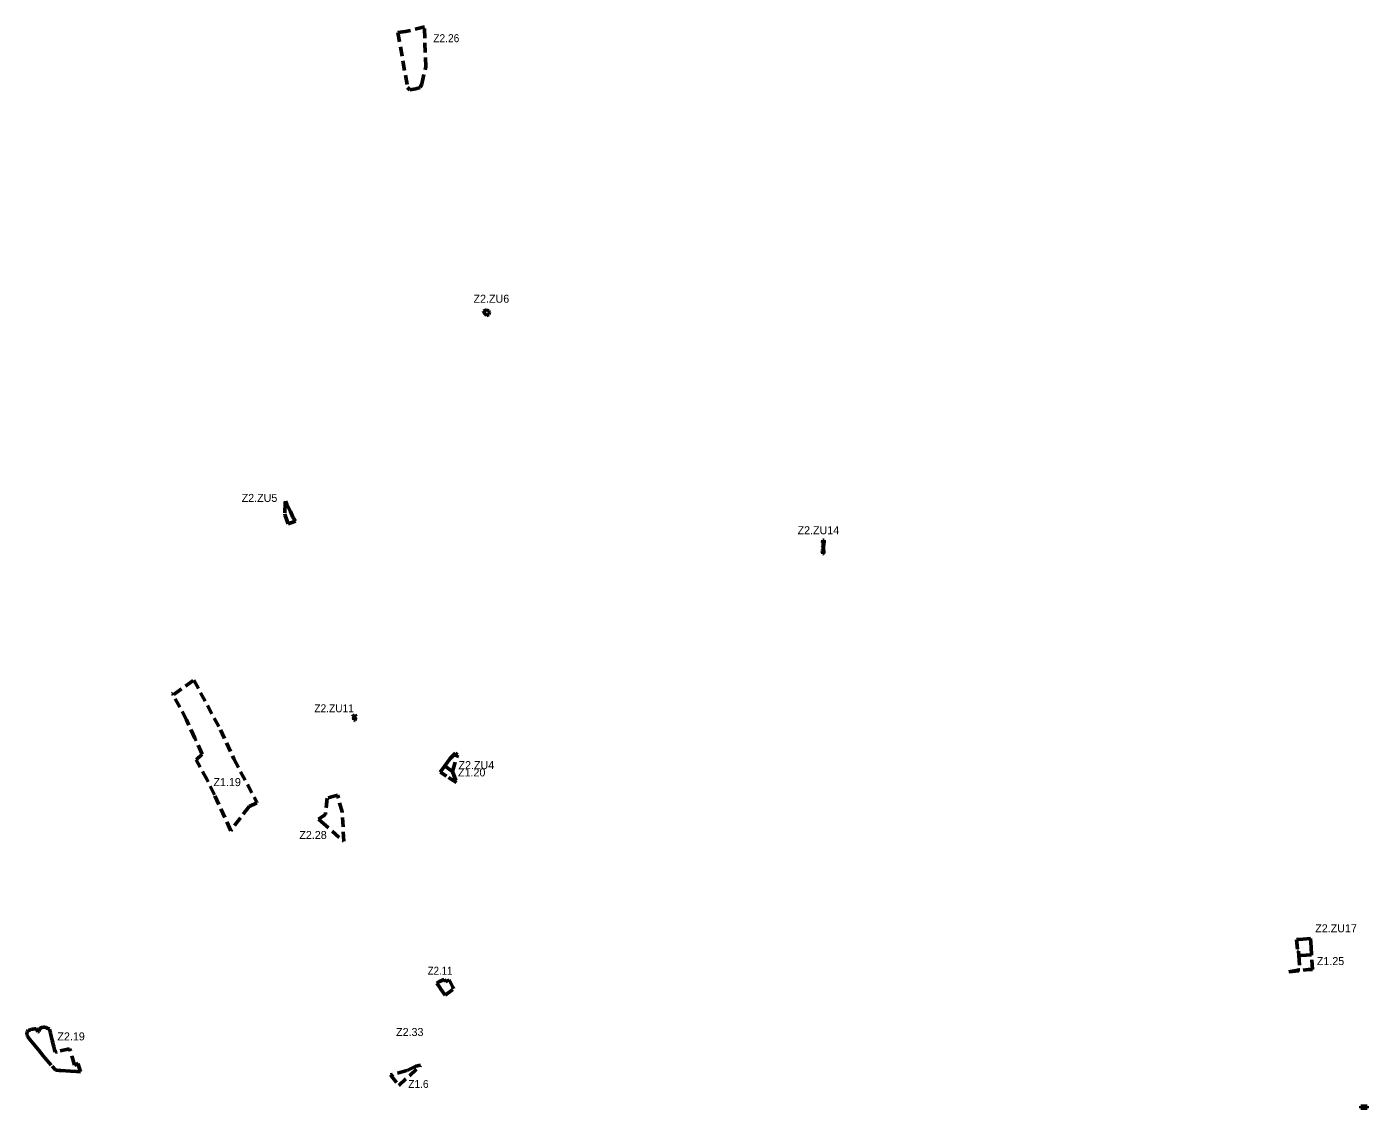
# Model space of a CAD drawing. Extents: x -650368 to -643203, y -1074215 to -1066658.
# Drawn here: x -646793 to -643276, y -1070330 to -1067493 of the extents above; entities that cross this region are included whole.
import ezdxf
from ezdxf.enums import TextEntityAlignment as Align

# ---------------------------------------------------------------- set-up
doc = ezdxf.new("R2010")
doc.units = 0
doc.header["$LTSCALE"] = 8.4
doc.linetypes.add('MEDIUM_DASHED', pattern=[4.5, 3, -1.5])
doc.layers.add('57', color=7, linetype='MEDIUM_DASHED', lineweight=40)
doc.layers.add('58', color=7, linetype='MEDIUM_DASHED', lineweight=53)
doc.layers.add('60', color=7, linetype='Continuous')
doc.layers.add('61', color=7, linetype='Continuous')

msp = doc.modelspace()

# ---------------------------------------------------------------- linework, layer by layer
at = {"layer": '57', "lineweight": 53}
for points in [[(-646410.74, -1069242.8), (-646409.21, -1069241.71), (-646407.33, -1069245.03), (-646354.82, -1069206.96), (-646284.98, -1069337.17), (-646249.6, -1069413.93), (-646190.68, -1069525.54), (-646189.17, -1069528.74), (-646209.9, -1069538.5), (-646258.086, -1069602.285), (-646300.42, -1069507.93), (-646319.61, -1069468.58), (-646348.36, -1069416.16), (-646332.84, -1069401.02), (-646351.69, -1069359.26), (-646373.91, -1069311.42), (-646408.81, -1069246.1)], [(-645694.21, -1069433.78), (-645678.454, -1069444.783), (-645675.91, -1069446.56), (-645665.58, -1069475.61), (-645692.107, -1069459.043), (-645706.8, -1069449.7), (-645708.48, -1069448.63), (-645696.45, -1069432.21)], [(-643481.78, -1069972.39), (-643430.64, -1069966.78), (-643419.43, -1069966.34), (-643422.2, -1069927.68), (-643455.292, -1069930.059), (-643452.63, -1069967.09), (-643455.6, -1069967.63), (-643458.57, -1069968.17), (-643468.026, -1069969.889)], [(-645838.53, -1070243.19), (-645816.9, -1070270.96), (-645760.05, -1070217.79), (-645772.08, -1070220.39), (-645795.85, -1070231.81), (-645833.92, -1070241.96)]]:
    msp.add_lwpolyline(points, close=True, dxfattribs=at)
at = {"layer": '58'}
for points in [[(-645819.48, -1067507.57), (-645793.94, -1067651.61), (-645788.395, -1067658.038), (-645782.72, -1067657.28), (-645772.13, -1067655.13), (-645760.67, -1067652.05), (-645756.491, -1067642.479), (-645746.448, -1067597.944), (-645749.67, -1067492.54), (-645786.52, -1067502.4), (-645799.72, -1067504.47)], [(-645594.36, -1068238.9), (-645586.3, -1068235.27), (-645580.62, -1068237.58), (-645578.75, -1068241.63), (-645580.9, -1068247.49), (-645587.06, -1068250.38), (-645590.885, -1068244.738), (-645594.58, -1068239.29)], [(-646110.72, -1068746.41), (-646114.15, -1068737.05), (-646115.07, -1068742.74), (-646115.86, -1068770.5), (-646115.26, -1068775.39), (-646107.5, -1068796.63), (-646088.06, -1068789.6), (-646094.58, -1068779.42), (-646100.92, -1068764.62)], [(-644704.63, -1068875.27), (-644703.98, -1068875.29), (-644701.79, -1068875.14), (-644701.59, -1068867.03), (-644702.51, -1068867.03), (-644702.41, -1068861.69), (-644701.42, -1068861.72), (-644701.38, -1068859.71), (-644702.34, -1068859.68), (-644702.08, -1068847.23), (-644701.42, -1068847.26), (-644701.09, -1068846.91), (-644700.9, -1068839.57), (-644704.8, -1068840.1), (-644705.08, -1068846.84), (-644704.81, -1068847.09), (-644703.68, -1068847.15), (-644704, -1068859.63), (-644704.74, -1068859.69), (-644705.53, -1068860.05), (-644706.03, -1068860.61), (-644705.56, -1068861.19), (-644704.79, -1068861.59), (-644703.94, -1068861.63), (-644704.08, -1068867.01), (-644705.38, -1068867.01), (-644705.95, -1068867.45), (-644706.19, -1068867.95), (-644706.2, -1068868.36), (-644704.91, -1068870.88), (-644704.56, -1068872.46)], [(-645938.32, -1069303.37), (-645935.71, -1069304.85), (-645934.38, -1069306.59), (-645934.21, -1069306.82), (-645934.66, -1069312.34), (-645934.17, -1069312.41), (-645931.98, -1069312.69), (-645931.24, -1069312.79), (-645930.48, -1069306.22), (-645931.2, -1069306.14), (-645931.07, -1069305.08), (-645933.12, -1069305.94), (-645928.65, -1069302.49), (-645932.07, -1069298.43), (-645936.46, -1069301.94)], [(-645675.91, -1069446.56), (-645663.41, -1069402.83), (-645668.61, -1069398.9), (-645678.06, -1069408.54), (-645682.28, -1069412.88), (-645696.45, -1069432.21), (-645694.21, -1069433.78)], [(-646004.7, -1069517.16), (-646009.52, -1069559.6), (-646017.39, -1069564.94), (-646027.49, -1069571.79), (-646020.4, -1069578.04), (-645961.36, -1069630.05), (-645965.36, -1069552.99), (-645977.73, -1069509.11)], [(-643422.204, -1069927.68), (-643423.64, -1069907.59), (-643425.25, -1069885.25), (-643445.37, -1069886.7), (-643461.33, -1069887.84), (-643459.13, -1069918.47), (-643456.14, -1069918.26), (-643455.292, -1069930.059), (-643455.292, -1069930.059), (-643450.3, -1069929.7)], [(-645695.39, -1070034), (-645673.1, -1070016.78), (-645675.24, -1070012.51), (-645681.339, -1070000.33), (-645684.59, -1069993.87), (-645689.84, -1069996.37), (-645694.8, -1069998.22), (-645697.59, -1069992.31), (-645710.43, -1069998.39), (-645717.36, -1070002.12), (-645709.434, -1070013.522), (-645706.41, -1070018.01)], [(-646784.13, -1070124.41), (-646787, -1070125.38), (-646788.77, -1070126.26), (-646789.61, -1070126.79), (-646791.03, -1070128.23), (-646791.64, -1070129), (-646792.11, -1070129.89), (-646792.76, -1070131.79), (-646792.97, -1070133.76), (-646792.84, -1070135.73), (-646792.42, -1070137.71), (-646792.18, -1070138.48), (-646791.84, -1070139.56), (-646791.13, -1070141.44), (-646790.86, -1070142.02), (-646790.29, -1070142.85), (-646784.8, -1070149.86), (-646775.93, -1070160.78), (-646762.52, -1070177.24), (-646749.79, -1070193.02), (-646745.61, -1070198.15), (-646726.48, -1070220.46), (-646726.36, -1070220.34), (-646719.7, -1070228.25), (-646717.71, -1070230.56), (-646717.71, -1070230.56), (-646714.42, -1070230.81), (-646708.2, -1070231.25), (-646703.67, -1070231.58), (-646677.99, -1070233.44), (-646662.41, -1070234.57), (-646651.86, -1070235.22), (-646656.96, -1070218.43), (-646658.64, -1070212.77), (-646667.64, -1070217.36), (-646680.61, -1070174.79), (-646680.68, -1070174.5), (-646713.74, -1070182.36), (-646718.8, -1070183.56), (-646721.09, -1070173.94), (-646722.4, -1070168.45), (-646723.4, -1070164.29), (-646724.86, -1070158.17), (-646725.39, -1070155.78), (-646726.17, -1070152.7), (-646728.14, -1070144.51), (-646730.45, -1070134.85), (-646730.97, -1070132.67), (-646731.54, -1070130.28), (-646733.35, -1070122.79), (-646740.92, -1070119.57), (-646743.33, -1070118.51), (-646745.78, -1070117.96), (-646748.31, -1070117.83), (-646753.45, -1070118.63), (-646755.74, -1070119.56), (-646757.76, -1070121.07), (-646759.06, -1070122.6), (-646759.78, -1070124), (-646760.32, -1070125.55), (-646760.5, -1070127.58), (-646760.22, -1070129.42), (-646762.07, -1070129.91), (-646763.9, -1070130.41), (-646763.98, -1070130.1), (-646764, -1070129.86), (-646764.94, -1070127.21), (-646765.19, -1070126.23), (-646765.51, -1070125.28), (-646765.97, -1070124.42), (-646767.38, -1070123), (-646768.25, -1070122.53), (-646769.17, -1070122.15), (-646770.43, -1070121.92), (-646772.19, -1070121.98), (-646777.37, -1070122.79), (-646780.28, -1070123.41)], [(-643293.29, -1070324.84), (-643293.27, -1070330.45), (-643285.64, -1070330.42), (-643276.25, -1070330.39), (-643276.27, -1070324.78), (-643283.69, -1070324.81)]]:
    msp.add_lwpolyline(points, close=True, dxfattribs=at)

# ---------------------------------------------------------------- texts
at = {"layer": '60'}
for s, p in [('Z1.19', (-646267.37, -1069485.175)), ('Z1.20', (-645625.728, -1069459.757)), ('Z1.25', (-643372.437, -1069954.895))]:
    msp.add_text(s, height=21, dxfattribs=at).set_placement(p, align=Align.CENTER)
at = {"layer": '60', "width": 0.95}
msp.add_text('Z1.6', height=21, dxfattribs=at).set_placement((-645765.49, -1070277.347), align=Align.CENTER)
at = {"layer": '61'}
for s, width, p in [('Z2.26', 0.95, (-645692.356, -1067532.999)), ('Z2.ZU11', 0.95, (-645986.653, -1069291.46)), ('Z2.11', 0.9, (-645708.736, -1069980.15))]:
    msp.add_text(s, height=21, dxfattribs=dict(at, width=width)).set_placement(p, align=Align.CENTER)
for s, p in [('Z2.ZU6', (-645574.084, -1068216.663)), ('Z2.ZU5', (-646182.477, -1068739.396)), ('Z2.ZU14', (-644716.167, -1068824.275)), ('Z2.ZU4', (-645613.502, -1069440.599)), ('Z2.28', (-646041.997, -1069623.92)), ('Z2.ZU17', (-643357.914, -1069868.835)), ('Z2.19', (-646676.745, -1070152.544)), ('Z2.33', (-645788.185, -1070141.025))]:
    msp.add_text(s, height=21, dxfattribs=at).set_placement(p, align=Align.CENTER)

doc.saveas('drawing.dxf')
